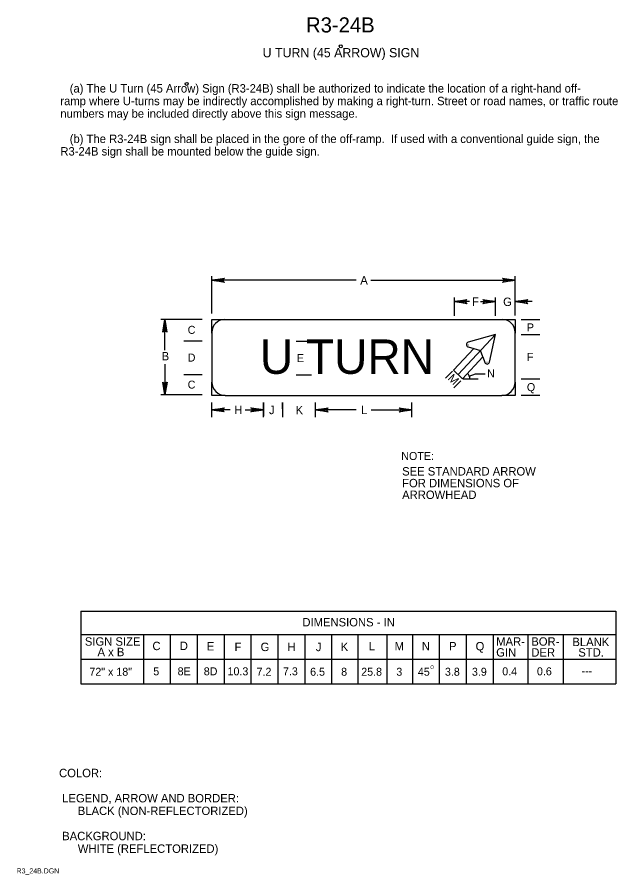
# Model space of a CAD drawing. Extents: x 0.5 to 7.5, y 0.2 to 10.2.
import ezdxf

# ---------------------------------------------------------------- set-up
doc = ezdxf.new("R2010")
doc.units = 0
for name, color, linetype in [('1', 7, 'Continuous'), ('11', 7, 'Continuous'), ('12', 7, 'Continuous'), ('2', 7, 'Continuous'), ('3', 7, 'Continuous')]:
    doc.layers.add(name, color=color, linetype=linetype)

# ---------------------------------------------------------------- blocks, each defined once
blk = doc.blocks.new('RARROW')
at = {"layer": '3'}
for p, q in [((-84.9, 11.2), (-89.2, 15.1)), ((-89.2, 15.1), (0, 0)), ((0, 0), (-89.2, -14.9)), ((-84.9, 11.2), (-81.7, 4.8)), ((0, 0), (-84.9, 11.2)), ((-84.6, -10.6), (0, 0)), ((-81.7, 4.8), (0, 0)), ((0, 0), (-81.7, -4.3)), ((-89.2, -14.9), (-84.6, -10.6)), ((-81.7, -4.3), (-84.6, -10.6))]:
    blk.add_line(p, q, dxfattribs=at)

msp = doc.modelspace()

# ---------------------------------------------------------------- linework, layer by layer
at = {"layer": '1'}
for centre in [(4.287, 9.863), (2.483, 9.422)]:
    msp.add_circle(centre, 0.0174, dxfattribs=at)
at = {"layer": '11'}
for p, q in [((2.777, 6.502), (2.777, 6.66)), ((2.777, 6.66), (2.935, 6.66)), ((6.171, 6.66), (6.329, 6.66)), ((6.329, 6.66), (6.329, 6.502)), ((2.777, 5.772), (2.777, 5.929)), ((6.329, 5.929), (6.329, 5.772)), ((2.935, 5.772), (2.777, 5.772)), ((6.329, 5.772), (6.171, 5.772))]:
    msp.add_line(p, q, dxfattribs=at)
at = {"layer": '12'}
for p, q in [((6.097, 6.487), (5.778, 6.395)), ((6.027, 6.161), (6.097, 6.487)), ((5.776, 6.341), (5.846, 6.321)), ((5.846, 6.321), (5.606, 6.07)), ((5.712, 5.966), (5.948, 6.225)), ((5.948, 6.225), (5.973, 6.159)), ((5.606, 6.07), (5.712, 5.966))]:
    msp.add_line(p, q, dxfattribs=at)
for centre, radius, start, end in [((5.785, 6.368), 0.0282, 104.7971, 250.7977), ((5.999, 6.168), 0.0281, 198.1274, 346.0897)]:
    msp.add_arc(centre, radius, start, end, dxfattribs=at)
at = {"layer": '3'}
for p, q in [((2.777, 6.734), (2.777, 7.17)), ((2.777, 7.121), (2.924, 7.145)), ((2.917, 7.138), (2.777, 7.121)), ((2.912, 7.128), (2.917, 7.138)), ((2.924, 7.145), (2.917, 7.138)), ((6.329, 6.722), (6.329, 7.17)), ((2.777, 7.121), (2.912, 7.128)), ((4.466, 7.121), (2.777, 7.121)), ((2.912, 7.113), (2.777, 7.121)), ((2.777, 7.121), (2.917, 7.103)), ((2.924, 7.096), (2.777, 7.121)), ((2.917, 7.103), (2.912, 7.113)), ((2.917, 7.103), (2.924, 7.096)), ((4.64, 7.121), (6.329, 7.121)), ((5.616, 6.847), (5.616, 6.921)), ((5.616, 6.704), (5.616, 6.921)), ((5.794, 6.871), (5.616, 6.871)), ((5.924, 6.871), (6.097, 6.871)), ((6.097, 6.706), (6.097, 6.921)), ((6.329, 6.707), (6.329, 6.921)), ((6.526, 6.871), (6.329, 6.871)), ((2.665, 6.662), (2.179, 6.662)), ((2.228, 6.304), (2.228, 6.662)), ((2.925, 6.66), (6.181, 6.66)), ((6.399, 6.66), (6.616, 6.66)), ((2.777, 6.512), (2.777, 5.929)), ((5.659, 6.018), (6.097, 6.487)), ((6.329, 5.929), (6.329, 6.512)), ((6.399, 6.487), (6.616, 6.487)), ((2.448, 6.413), (2.665, 6.413)), ((3.764, 6.407), (3.944, 6.407)), ((5.846, 6.321), (5.923, 6.3)), ((5.948, 6.225), (5.923, 6.3)), ((2.228, 6.14), (2.228, 5.781)), ((5.594, 6.058), (5.512, 5.974)), ((2.448, 6.018), (2.665, 6.018)), ((3.764, 6.013), (3.944, 6.013)), ((5.692, 5.944), (5.609, 5.86)), ((5.72, 5.966), (5.896, 5.966)), ((6.399, 5.966), (6.616, 5.966)), ((2.228, 5.781), (2.203, 5.929)), ((2.203, 5.929), (2.21, 5.921)), ((2.221, 5.916), (2.21, 5.921)), ((2.21, 5.921), (2.228, 5.781)), ((2.228, 5.781), (2.221, 5.916)), ((2.253, 5.929), (2.228, 5.781)), ((2.228, 5.781), (2.246, 5.922)), ((2.236, 5.917), (2.228, 5.781)), ((2.246, 5.922), (2.236, 5.917)), ((2.246, 5.922), (2.253, 5.929)), ((2.665, 5.781), (2.179, 5.781)), ((2.935, 5.772), (6.171, 5.772)), ((6.616, 5.772), (6.399, 5.772)), ((2.776, 5.517), (2.776, 5.69)), ((3.383, 5.69), (3.383, 5.53)), ((3.383, 5.517), (3.383, 5.69)), ((3.605, 5.69), (3.605, 5.517)), ((3.605, 5.616), (3.605, 5.69)), ((3.992, 5.517), (3.992, 5.69)), ((5.119, 5.517), (5.119, 5.69)), ((2.993, 5.603), (2.776, 5.603)), ((3.166, 5.603), (3.383, 5.603)), ((4.468, 5.602), (3.992, 5.602)), ((4.642, 5.602), (5.119, 5.602)), ((1.242, 3.243), (1.242, 2.392)), ((1.242, 3.243), (7.506, 3.243)), ((7.506, 3.243), (7.506, 2.392)), ((1.242, 2.972), (7.506, 2.972)), ((1.976, 2.972), (1.976, 2.392)), ((2.291, 2.972), (2.291, 2.392)), ((2.606, 2.972), (2.606, 2.392)), ((2.921, 2.972), (2.921, 2.392)), ((3.235, 2.972), (3.235, 2.392)), ((3.55, 2.972), (3.55, 2.392)), ((3.865, 2.972), (3.865, 2.392)), ((4.18, 2.972), (4.18, 2.392)), ((4.485, 2.972), (4.485, 2.392)), ((4.825, 2.972), (4.825, 2.392)), ((5.125, 2.972), (5.125, 2.392)), ((5.44, 2.972), (5.44, 2.392)), ((5.755, 2.972), (5.755, 2.392)), ((6.07, 2.972), (6.07, 2.392)), ((6.477, 2.972), (6.477, 2.392)), ((6.888, 2.972), (6.888, 2.392)), ((1.242, 2.682), (7.506, 2.682)), ((1.242, 2.392), (7.506, 2.392))]:
    msp.add_line(p, q, dxfattribs=at)
msp.add_lwpolyline([(5.791, 5.999), (5.862, 6.027), (5.976, 6.027)], dxfattribs=at)
for centre, radius, start, end in [((2.925, 6.512), 0.148, 90, 180), ((6.181, 6.512), 0.148, 0, 90), ((5.712, 5.966), 0.0862, 47.6603, 47.6603), ((5.712, 5.966), 0.0862, 0, 47.6603), ((2.935, 5.929), 0.158, 180, 270), ((6.171, 5.929), 0.158, 270, 0)]:
    msp.add_arc(centre, radius, start, end, dxfattribs=at)

# ---------------------------------------------------------------- block references
at = {"layer": '3', "xscale": 0.0016545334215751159, "yscale": 0.0016366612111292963}
for p in [(6.329, 7.121), (6.097, 6.871), (3.383, 5.603), (5.119, 5.602)]:
    msp.add_blockref('RARROW', p, dxfattribs=at)
for p, rotation in [((5.616, 6.871), 180), ((6.329, 6.871), 180), ((2.228, 6.662), 90), ((2.776, 5.603), 180), ((3.992, 5.602), 180)]:
    msp.add_blockref('RARROW', p, dxfattribs=dict(at, rotation=rotation))

# ---------------------------------------------------------------- texts
at = {"layer": '1'}
for s, height, p in [('R3-24B', 0.1772, (3.88, 10.025)), ('U TURN (45 ARROW) SIGN', 0.10828, (3.372, 9.734)), ('NOTE:', 0.0935, (4.995, 5.016)), ('SEE STANDARD ARROW', 0.09842, (5.005, 4.834)), ('FOR DIMENSIONS OF', 0.09842, (5.005, 4.696)), ('ARROWHEAD', 0.0984, (5.005, 4.559)), ('COLOR:', 0.0984, (0.989, 1.299)), (' LEGEND, ARROW AND BORDER:', 0.09842, (0.989, 1.004)), ('      BLACK (NON-REFLECTORIZED)', 0.09842, (0.989, 0.856)), (' BACKGROUND:', 0.09842, (0.989, 0.561)), ('      WHITE (REFLECTORIZED)', 0.09842, (0.989, 0.413)), ('R3_24B.DGN', 0.0591, (0.492, 0.172))]:
    msp.add_text(s, height=height, dxfattribs=at).set_placement(p)
at = {"layer": '12'}
msp.add_text('U TURN', height=0.4033, dxfattribs=at).set_placement((3.34, 6.025))
msp.add_text('+', height=0.031, rotation=46.8172, dxfattribs=at).set_placement((5.782, 6.344))
at = {"layer": '2'}
for s, height, p in [('   (a) The U Turn (45 Arrow) Sign (R3-24B) shall be authorized to indicate the location of a right-hand off- ', 0.098415, (1.004, 9.321)), ('ramp where U-turns may be indirectly accomplished by making a right-turn. Street or road names, or traffic route ', 0.098415, (1.004, 9.173)), ('numbers may be included directly above this sign message.', 0.09842, (1.004, 9.026)), ('   (b) The R3-24B sign shall be placed in the gore of the off-ramp.  If used with a conventional guide sign, the ', 0.098415, (1.004, 8.73)), ('R3-24B sign shall be mounted below the guide sign. ', 0.09842, (1.004, 8.583))]:
    msp.add_text(s, height=height, dxfattribs=at).set_placement(p)
at = {"layer": '3'}
for s, height, p in [('A', 0.0984, (4.515, 7.072)), ('F', 0.0984, (5.823, 6.822)), ('G', 0.0984, (6.187, 6.82)), ('C', 0.0935, (2.495, 6.494)), ('P', 0.0935, (6.465, 6.523)), ('B', 0.0984, (2.19, 6.183)), ('D', 0.0935, (2.495, 6.169)), ('E', 0.0935, (3.773, 6.163)), ('F', 0.0935, (6.465, 6.177)), ('N', 0.0935, (6, 5.983)), ('C', 0.0935, (2.495, 5.852)), ('Q', 0.0935, (6.465, 5.823)), ('H', 0.0984, (3.04, 5.554)), ('J', 0.0984, (3.446, 5.553)), ('K', 0.0984, (3.758, 5.551)), ('L', 0.0984, (4.523, 5.553)), ('DIMENSIONS - IN', 0.09842, (3.837, 3.066)), ('SIGN SIZE', 0.0984, (1.291, 2.84)), ('MAR-', 0.0984, (6.106, 2.84)), ('BOR-', 0.0984, (6.517, 2.84)), ('BLANK', 0.0984, (6.998, 2.835)), ('A x B', 0.0984, (1.439, 2.717)), ('C', 0.0984, (2.082, 2.788)), ('D', 0.0984, (2.402, 2.789)), ('E', 0.0984, (2.718, 2.784)), ('F', 0.0984, (3.043, 2.778)), ('G', 0.0984, (3.348, 2.777)), ('H', 0.0984, (3.663, 2.777)), ('J', 0.0984, (3.994, 2.776)), ('K', 0.0984, (4.286, 2.778)), ('L', 0.0984, (4.614, 2.785)), ('M', 0.0984, (4.917, 2.785)), ('N', 0.0984, (5.235, 2.785)), ('P', 0.0984, (5.554, 2.785)), ('Q', 0.0984, (5.865, 2.785)), ('GIN', 0.0984, (6.106, 2.712)), ('DER', 0.0984, (6.517, 2.712)), ('STD.', 0.0984, (7.067, 2.712)), ('72" x 18"', 0.0935, (1.344, 2.488)), ('5', 0.0935, (2.092, 2.493)), ('8E', 0.0935, (2.377, 2.493)), ('8D', 0.0935, (2.683, 2.493)), ('10.3', 0.0935, (2.961, 2.493)), ('7.2', 0.0935, (3.301, 2.488)), ('7.3', 0.0935, (3.61, 2.493)), ('6.5', 0.0935, (3.928, 2.488)), ('8', 0.0935, (4.291, 2.488)), ('25.8', 0.0935, (4.526, 2.488)), ('3', 0.0935, (4.937, 2.488)), ('45', 0.0935, (5.189, 2.488)), ('O', 0.04, (5.334, 2.568)), ('3.8', 0.0935, (5.506, 2.488)), ('3.9', 0.0935, (5.822, 2.488)), ('0.4', 0.0935, (6.177, 2.493)), ('0.6', 0.0935, (6.583, 2.493)), ('---', 0.0935, (7.105, 2.499))]:
    msp.add_text(s, height=height, dxfattribs=at).set_placement(p)
for s, height, rotation, p in [('+', 0.031, 46.9263, (6, 6.14)), ('M', 0.0984, 315.5673, (5.532, 5.964))]:
    msp.add_text(s, height=height, rotation=rotation, dxfattribs=at).set_placement(p)

doc.saveas('drawing.dxf')
